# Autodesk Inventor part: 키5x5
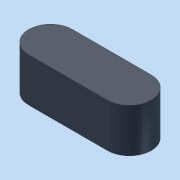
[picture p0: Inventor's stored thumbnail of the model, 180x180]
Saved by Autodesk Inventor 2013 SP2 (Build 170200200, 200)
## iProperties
Company: 한국ATC센터
Created: 2014-12
Part Number: 키5x5
Document SubType Name: Modeling
Designer: KYOUNG IL JANG
Density: 1 g/cm^3
Mass: 0.323175 g
Surface Area: 2.9781 cm^2
Volume: 0.323175 cm^3
Material: 일반
Author: KYOUNG IL JANG
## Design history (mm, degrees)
sketch "스케치1"
  geometry: L1 (-4.5, -2.5)-(4.5, -2.5) reference; L2 (4.5, 2.5)-(-4.5, 2.5) reference; A1 r 2.5 centre (-4.5, 0) between (-4.5, 2.5) and (-4.5, -2.5) reference; A2 r 2.5 centre (4.5, 0) between (4.5, -2.5) and (4.5, 2.5) reference; 1 further point
extrude "돌출1" new body sketch "스케치1" distance "d0" = 5; taper "d1" = 0 deg
node "솔리드1"
node "참조1"
